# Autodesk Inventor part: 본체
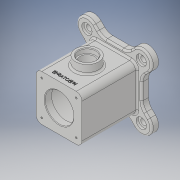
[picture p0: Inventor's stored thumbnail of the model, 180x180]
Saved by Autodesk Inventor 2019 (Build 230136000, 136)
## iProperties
Created: 2021-01
Part Number: 본체
Material: 일반
Document SubType Name: Modeling
Designer: 3dpro0
Density: 1 g/cm^3
Appearance: 기본값
Mass: 385.865 g
Surface Area: 854.376 cm^2
Volume: 385.865 cm^3
Author: 3dpro0
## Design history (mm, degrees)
sketch "스케치1"
  geometry: L1 (-40, -40)-(40, -40); L2 (40, -40)-(40, 40); L3 (40, 40)-(-40, 40); L4 (-40, 40)-(-40, -40); L5 (-40, -40)-(40, 40); L6 (40, -40)-(-40, 40); 1 further point
  constraints: 12 end point, 2 midpoint, 2 parallel, 1 horizontal, 1 perpendicular
  dimensions: "d0" = 80 distance of L3.end L2.end; "d1" = 80 distance of L2.end L1.end
extrude "돌출1" new body sketch "스케치1" distance "d2" = 108; taper "d3" = 0 deg
sketch "스케치2"
  geometry: L1 (-48, -48)-(48, -48); L2 (48, -48)-(48, 48); L3 (48, 48)-(-48, 48); L4 (-48, 48)-(-48, -48); L5 (-48, -48)-(48, 48); L6 (48, -48)-(-48, 48); 1 further point
  constraints: 12 end point, 2 midpoint, 2 parallel, 1 horizontal, 1 perpendicular
  dimensions: "d4" = 96 distance of L3.end L2.end; "d5" = 96 distance of L2.end L1.end
extrude "돌출2" join sketch "스케치2" distance "d6" = 12; taper "d7" = 0 deg
sketch "스케치3"
  geometry: L1 (48, 48)-(-48, 48) reference; L2 (48, -48)-(48, 48) reference; L3 (0, 0)-(47.376, 47.376); L4 (0, 0)-(67, 0); L5 (34.648, 60.104)-(22.544, 48); L6 (60.104, 34.648)-(48, 22.544); A1 r 18 centre (47.376, 47.376) between (60.104, 34.648) and (34.648, 60.104)
  constraints: 8 end point, 2 point on circle, 2 point on line, 2 tangent, 1 centre point, 1 coincident, 1 equal length, 1 horizontal, 1 parallel
  dimensions: "d8" = 67 distance of L3.start L3.end; "d9" = 45 deg angle of L4 L3; "d10" = 36 diameter of A1
extrude "돌출3" join sketch "스케치3" distance "d11" = 12; taper "d12" = 0 deg
sketch "스케치4"
  geometry: C1 r 25 at (0, 0); 1 further point
  constraints: 1 centre point, 1 coincident
  dimensions: "d16" = 50 diameter of C1
extrude "돌출4" cut sketch "스케치4" extent not by distance; stored distance "d17" = 12; taper "d18" = 0 deg
node "작업 평면1"
sketch "스케치5"
  geometry: C1 r 35 at (0, 0); 1 further point
  constraints: 1 centre point, 1 coincident
  dimensions: "d20" = 70 diameter of C1
extrude "돌출5" cut sketch "스케치5" distance "d21" = 84; taper "d22" = 0 deg
sketch "스케치6"
  geometry: L1 (62.544, 108)-(17.456, 108) reference; C1 r 20 at (40, 49); 2 further points
  constraints: 1 centre point, 1 midpoint, 1 vertical alignment
  dimensions: "d23" = 40 diameter of C1; "d24" = 59 distance from line of C1.centre L1
extrude "돌출6" join sketch "스케치6" distance "d25" = 15; taper "d26" = 0 deg
sketch "스케치7"
  geometry: C1 r 20 at (0, 0) reference; 2 further points
  constraints: 1 coincident
hole "구멍1" sketch "스케치7" at (0, 0) diameter "d27" = 25; stored, may be unused: countersink angle "d31" = 90 deg, drill point angle "d33" = 118 deg; dims "d28" = 8, "d29" = 30, "d30" = 8, "d32" = 10
sketch "스케치8"
  geometry: L1 (-30, -30)-(30, -30); L2 (30, -30)-(30, 30); L3 (30, 30)-(-30, 30); L4 (-30, 30)-(-30, -30); L5 (-30, -30)-(30, 30); L6 (30, -30)-(-30, 30); 4 further points
  constraints: 12 end point, 3 coincident, 2 midpoint, 2 parallel, 1 horizontal, 1 perpendicular
  dimensions: "d34" = 60 distance of L3.end L2.end; "d35" = 60 distance of L2.end L1.end
hole "구멍2" sketch "스케치8" at (30, -30), (-30, -30), (30, 30), (-30, 30) diameter "d36" = 3.242; stored, may be unused: countersink angle "d40" = 90 deg, drill point angle "d42" = 118 deg; dims "d37" = 8, "d38" = 30, "d39" = 8, "d41" = 10
node "작업 평면2"
sketch "스케치9"
  geometry: L1 (80, 0)-(0, 0) reference; L2 (62.544, 108)-(17.456, 108) reference; 3 further points
  constraints: 1 midpoint, 1 vertical alignment, 1 other
  dimensions: "d44" = 10 distance from line of L1 point (40, 10)
feature "엠보싱1" sketch "스케치9" dims "d0" = 80, "d1" = 80, "d8" = 67, "d9" = 45 deg, "d10" = 36, "d45" = 0.5, "d46" = 0
sketch "스케치10"
  geometry: A1 r 18 centre (47.376, 47.376) between (60.104, 34.648) and (34.648, 60.104) reference; 2 further points
  constraints: 1 coincident
hole "구멍3" sketch "스케치10" at (47.376, 47.376) diameter "d47" = 10; stored, may be unused: countersink angle "d51" = 90 deg, drill point angle "d53" = 118 deg; dims "d48" = 8, "d49" = 18, "d50" = 4, "d52" = 10
fillet "모깎기1" dims "d57" = 10
fillet "모깎기2" dims "d58" = 20
fillet "모깎기3" dims "d59" = 3
chamfer "모따기1" distance "d60" = 1; stored, may be unused: second distance "d61" = 2, angle "d62" = 45 deg
node "솔리드1"
pattern_circular "원형 패턴1" dims angle "d14" = 360 deg
mirror "미러1"
pattern_circular "원형 패턴2" dims angle "d55" = 360 deg
other parameters: "d19" = -12, "d43" = -54
